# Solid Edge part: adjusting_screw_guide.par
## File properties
Title: Adjusting screw guide
Author: Robert a Rhodes jr
Template: Normal.par
Last saved by: TIET
Revision: 10
Application: Solid Edge
Density: 0 kg/mm^3
Accuracy: 0.99
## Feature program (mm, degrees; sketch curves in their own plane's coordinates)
sketch for "unnamed Protrusion 1" plane through (0, 0, 0) normal (0, -1, 0) x-axis (1, 0, 0)
  circle centre (0, 0) radius 12.7
extrude "unnamed Protrusion 1" add finite 63.5 along +normal
sketch for "ExtrudedProtrusion_2" plane through (0, -63.5, 0) normal (0, -1, 0) x-axis (1, 0, 0)
  circle centre (0, 0) radius 9.525
extrude "ExtrudedProtrusion_2" add finite 76.2 along +normal
chamfer "Chamfer_1" setback 1.5748
sketch for "ExtrudedCutout_1" plane through (0, 0, 0) normal (0, 0, 1) x-axis (1, 0, 0)
  line (1.1811, 0) -> (1.1811, -9.398)
  line (1.1811, -9.398) -> (-1.1811, -9.398)
  line (-1.1811, -9.398) -> (-1.1811, 0)
  line (-1.1811, 0) -> (1.1811, 0)
extrude "ExtrudedCutout_1" cut finite 101.6 symmetric
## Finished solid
Body 1: solid body, 10 faces, 16 edges, 8 vertices.
  Faces by surface: plane 7, cylinder 2, cone 1
  Edges by curve: circle 8, line 8
Bounding box of the edges (mm): 25.400 x 139.700 x 25.400, from (-12.7, -139.7, -12.7) to (12.7, 0, 12.7).
Cylindrical faces by radius (mm): R9.525 x1, R12.7 x1
Conical faces (half-angle, radius in mm at the cone's reference point): 45 deg R9.525 x1
Planar faces by outward normal: +x 1, +y 3, -x 1, -y 2
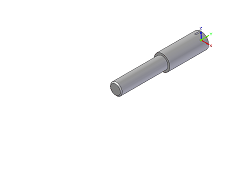
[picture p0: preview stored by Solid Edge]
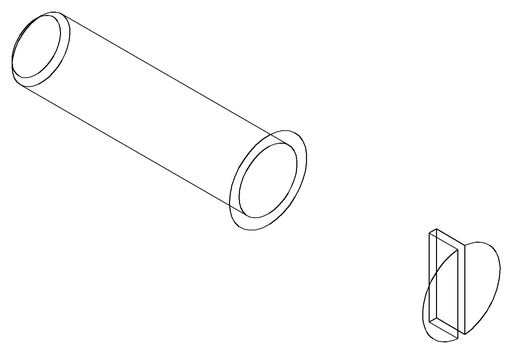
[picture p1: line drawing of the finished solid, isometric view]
